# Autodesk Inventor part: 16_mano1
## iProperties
Created: 2002-11
Part Number: 16_mano1
Material: Par défaut
Document SubType Name: Modélisation
Designer: FIEVET
Control State: 0
Master: False
Checked Out: False
Shininess: 86.0
Length Units: 11269
Angle Units: 11279
Time Units: 11290
Mass Units: 11283
Length Display Precision: 3
Angle Display Precision: 2
Compacted: True
Density: 0.0
Volumn: 0.0
Area: 0.0
PropertySet Name: Model Information
Author: FIEVET
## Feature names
1. Révolution1 [Revolution]
2. Extrusion1
3. Extrusion2
